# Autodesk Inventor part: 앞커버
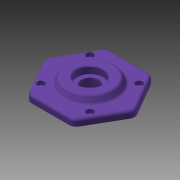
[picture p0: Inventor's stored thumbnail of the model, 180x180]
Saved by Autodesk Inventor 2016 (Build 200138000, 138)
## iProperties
Created: 2013-02
Part Number: 앞커버
Document SubType Name: Modeling
Density: 1 g/cm^3
Material: 일반
Appearance: 보라색
Author: 한국산업디자인학원[gmhk.co.kr]
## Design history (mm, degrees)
sketch "스케치1" dims "d37" = 105
  geometry: L1 (28.559, 41.466)-(50.191, 4); L2 (50.191, -4)-(28.559, -41.466); L3 (21.631, -45.466)-(-21.631, -45.466); L4 (-28.559, -41.466)-(-50.191, -4); L5 (-50.191, 4)-(-28.559, 41.466); L6 (-21.631, 45.466)-(21.631, 45.466); C1 r 30 at (0, 0); A1 r 8 centre (-43.262, 0) between (-50.191, 4) and (-50.191, -4); A2 r 8 centre (-21.631, 37.466) between (-21.631, 45.466) and (-28.559, 41.466); A3 r 8 centre (21.631, 37.466) between (28.559, 41.466) and (21.631, 45.466); A4 r 8 centre (43.262, 0) between (50.191, -4) and (50.191, 4); A5 r 8 centre (21.631, -37.466) between (21.631, -45.466) and (28.559, -41.466); A6 r 8 centre (-21.631, -37.466) between (-28.559, -41.466) and (-21.631, -45.466); 9 further points
  constraints: 12 end point, 12 point on circle, 12 point on line, 12 tangent, 7 centre point, 5 equal radius, 3 coincident, 1 horizontal, 16 other
  dimensions: "d40" = 8 radius of A1; "d41" = 60 diameter of C1
extrude "돌출1" new body sketch "스케치1" distance "d0" = 8; taper "d1" = 0 deg
sketch "스케치2"
  geometry: C1 r 30 at (0, 0); 1 further point
  constraints: 1 centre point, 1 coincident
  dimensions: "d2" = 60 diameter of C1
extrude "돌출2" join sketch "스케치2" distance "d3" = 7; taper "d4" = -30 deg
hole "구멍1" diameter "d7" = 20; stored, may be unused: countersink angle "d11" = 90 deg, drill point angle "d13" = 118 deg; dims "d8" = 6, "d9" = 30, "d10" = 8.3, "d12" = 20, "d52" = 10, "d53" = 10
sketch "스케치3"
  geometry: L1 (-28.284, 28.284)-(0, 0); L2 (0, 0)-(0, 40); L3 (0, 0)-(28.284, 28.284); L4 (0, 0)-(28.284, -28.284); L5 (0, 0)-(-28.284, -28.284); C1 r 1.621 at (28.284, 28.284); C2 r 1.621 at (-28.284, 28.284); C3 r 1.621 at (-28.284, -28.284); C4 r 1.621 at (28.284, -28.284); C5 r 10 at (0, 0) reference; A1 r 40 centre (0, 0) between (28.284, 28.284) and (-28.284, 28.284)
  constraints: 10 end point, 5 centre point, 3 perpendicular, 3 point on circle, 1 coincident, 1 vertical
  dimensions: "d48" = 80 diameter of A1; "d50" = 45 deg angle of L2 L1
hole "구멍2" sketch "스케치3" at (28.284, 28.284), (28.284, -28.284), (-28.284, -28.284), (-28.284, 28.284) diameter "d14" = 4.5; stored, may be unused: countersink angle "d18" = 90 deg, drill point angle "d20" = 118 deg; dims "d15" = 6, "d16" = 8, "d17" = 4.4, "d19" = 20
extrude "돌출3" join sketch "스케치1" distance "d21" = 12; taper "d22" = 0 deg
hole "구멍3" diameter "d25" = 30; stored, may be unused: countersink angle "d29" = 90 deg, drill point angle "d31" = 0 deg; dims "d26" = 6, "d27" = 40, "d28" = 12, "d30" = 15, "d42" = 10, "d43" = 10
fillet "모깎기1" dims "d32" = 3, "d33" = 0.3
chamfer "모따기1" distance "d34" = 1; stored, may be unused: second distance "d35" = 2, angle "d36" = 45 deg
chamfer "모따기2" distance "d44" = 1; stored, may be unused: second distance "d45" = 2, angle "d46" = 45 deg
fillet "모깎기2" dims "d47" = 3
fillet "모깎기3" dims "d54" = 0.6
node "솔리드1"
